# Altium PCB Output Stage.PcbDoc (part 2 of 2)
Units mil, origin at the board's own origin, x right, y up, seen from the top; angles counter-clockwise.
Board outline 5000 x 8750 mil, 6 copper layers (Top Layer, Layer 1, Layer 2, Layer 3, Layer 4, Bottom Layer), stack 91 mil thick; 55 components, 34 nets, 272 pads, 65 vias.
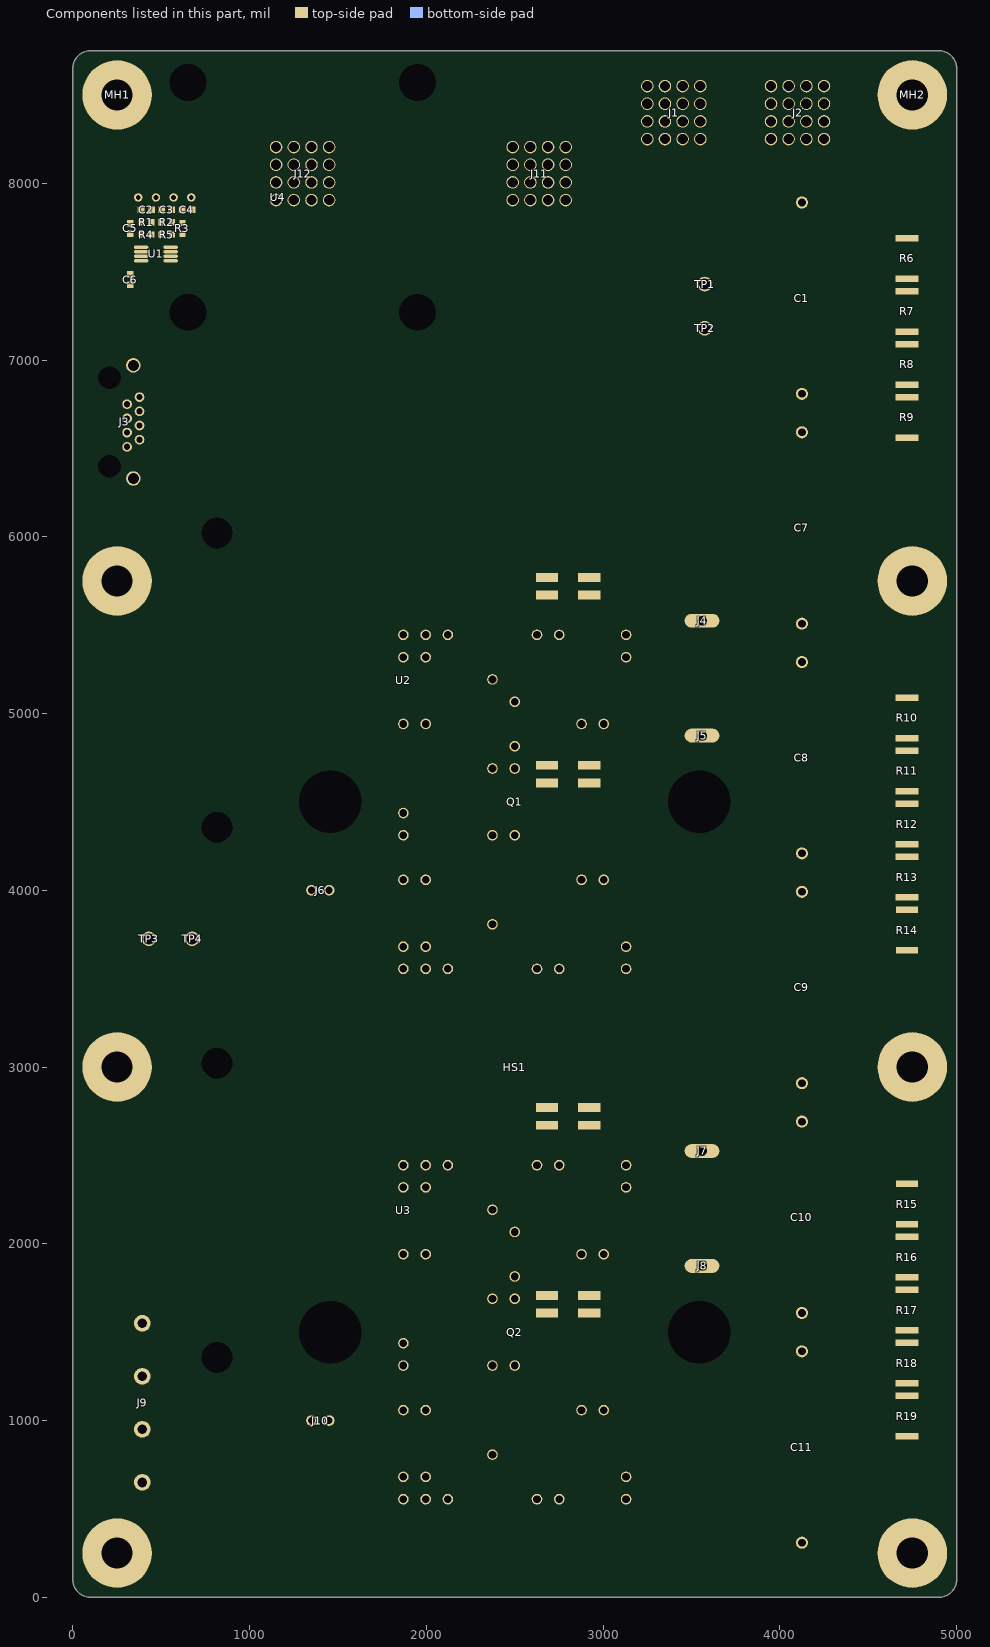
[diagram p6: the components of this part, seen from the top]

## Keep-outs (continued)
Layer 3:
  circle w15: c3501,5525 r47.17
  circle w15: c3619,5525 r47.17
  circle w15: c3501,2525 r47.17
  circle w15: c3619,2525 r47.17
  region: 2146.02,7015 2146.02,7525 2060,7525 2060,7015
  region: 2148.23,6965 2148.23,7578.68 2117.62,7578.68 2117.62,6965
  rectangle: 3965,2695 4285,2910
  rectangle: 3965,5295 4285,5510
  region: 2530.34,3795.34 2530.34,4045.34 2355,4045.34 2355,3795.34
  region: 2530.34,795.34 2530.34,1045.34 2355,1045.34 2355,795.34
  rectangle: 3035.75,1265.75 3400,1505
  rectangle: 3035.75,4265.75 3400,4505
  rectangle: 2935.34,1649.66 3185.34,1709.66
  rectangle: 2935,4650 3185,4710
  rectangle: 3500,5470 3620,5580
  rectangle: 3500,2470 3620,2580
  region: 3335.22,1875 3784.78,1875 3816.99,1546.5 3269.63,1546.5
  region: 3335.22,4875 3784.78,4875 3816.99,4546.5 3269.63,4546.5
  lines w10: 195,2585 cw(c295,2585) 295,2685 ; 195,3415 ccw(c295,3415) 295,3315 ; 625,7045.79 cw(c625,6945.79) 725,6945.79 ; 625,7495 ccw(c625,7595) 725,7595 ; 1955,7045.79 cw(c1955,6845.79) 2155,6845.79 ; 1955,7495 ccw(c1955,7695) 2155,7695 ; 1990,815 cw(c1990,765) 2040,765 ; 2072.64,756.36 cw(c2108,721) 2143.36,756.36 ; 2315,562 cw(c2415,562) 2415,662 ; 2315,3562 cw(c2415,3562) 2415,3662 ; 2525,965 cw(c2575,965) 2575,1015 ; 2525,3965 cw(c2575,3965) 2575,4015 ; 2790,1225 cw(c2840,1225) 2840,1275 ; 2790,4225 cw(c2840,4225) 2840,4275 ; 3870,195 ccw(c3870,295) 3970,295 ; 4275,275 ccw(c4355,275) 4355,195 ccw(c4355,275) 4435,275 ; 4705,565 ccw(c4705,665) 4805,665 ; 4705,2685 cw(c4705,2585) 4805,2585 ; 4705,3315 ccw(c4705,3415) 4805,3415 ; 4705,5435 cw(c4705,5335) 4805,5335 ; 4705,6065 ccw(c4705,6165) 4805,6165
Bottom Layer:
  circle w15: c3501,5525 r47.17
  circle w15: c3619,5525 r47.17
  circle w15: c3501,2525 r47.17
  circle w15: c3619,2525 r47.17
  rectangle: 3500,5470 3620,5580
  rectangle: 3500,2470 3620,2580
  region: 3301.15,4875 3816.99,4875 3816.99,4546.5 3269.63,4546.5
  region: 3301.15,1875 3816.99,1875 3816.99,1546.5 3269.63,1546.5
  lines w10: 195,2550 cw(c295,2550) 295,2650 ; 2315,572.17 cw(c2365,572.17) 2365,622.17 ; 2315,1042 ccw(c2365,1042) 2365,992 ; 2315,3572.17 cw(c2365,3572.17) 2365,3622.17 ; 2315,4042 ccw(c2365,4042) 2365,3992 ; 3835,195 ccw(c3835,295) 3935,295 ; 4305,245 ccw(c4355,245) 4355,195 ; 4348,195 ccw(c4348,245) 4398,245 ; 4705,600 ccw(c4705,700) 4805,700 ; 4705,2650 cw(c4705,2550) 4805,2550 ; 4705,3350 ccw(c4705,3450) 4805,3450 ; 4705,5400 cw(c4705,5300) 4805,5300 ; 4705,6100 ccw(c4705,6200) 4805,6200

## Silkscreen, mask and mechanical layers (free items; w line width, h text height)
Top Overlay:
  drawing of 107 lines, arcs and shapes, not listed
  text "-" at 4051.54,8013.08 h400
  text "+" at 3315.44,7978.62 h400
  text "A" at 1180.17,7550 h400
  text "B" at 2541.8,7550 h400
  text "+" at 3346.52,7329.71 h180
  text "-" at 3346.52,7064.71 h180
  text "A" at 336.52,3494.71 h180
  text "B" at 581.52,3494.71 h180
  text "WOLFPACK 60KW DAB (OUTPUT STAGE) / PN CRD60DD12N-GMA, V1 10/2023" at 363.05,55 h180
Mechanical 1:
  rectangle: 0,3500 5000,8500
Board Outline:
  the board outline again, w1
Drill Drawing:
  drawing of 171 lines, arcs and shapes, not listed
  text "*" at 150,11885 h60
  text "THESE HOLES (1.10MM +/- 0.05MM) ARE FOR PRESS-FIT PART. USE 47.2MIL +/- 1MIL DRILLED HOLES. COPPER THICKNESS IN HOLE 25-50UM." at 242.5,11827.5 h100
  text "w" at 16.81,11802.22 h200
  text "^" at 155,11700.01 h60
  text "THESE HOLES (1.48MM +/- 0.05MM) ARE FOR PRESS-FIT PART. USE 63.0MIL +/- 1MIL DRILLED HOLES. COPPER THICKNESS IN HOLE 25-60UM." at 247.5,11632.5 h100
  text "w" at 23.35,11614.16 h200
  text "Symbol" at 97.5,11452.5 h72
  text "Count" at 603.38,11452.5 h72
  text "Hole Size" at 1203.22,11452.5 h72
  text "Plated" at 2302.9,11452.5 h72
  text "Hole Type" at 2808.77,11452.5 h72
  text "Drill Layer Pair" at 3542.57,11452.5 h72
  text "Via/Pad" at 5042.13,11452.5 h72
  text "Pad Shape" at 5631.97,11452.5 h72
  text "Hole Tolerance (+)" at 6377.77,11452.5 h72
  text "Hole Tolerance (-)" at 7711.38,11452.5 h72
  text "65" at 603.38,11302.5 h60
  text "0.51mm (20.00mil)" at 1203.22,11302.5 h60
  text "PTH" at 2302.9,11302.5 h60
  text "Round" at 2808.77,11302.5 h60
  text "Top Layer - Bottom Layer" at 3542.57,11302.5 h60
  text "Via" at 5042.13,11302.5 h60
  text "Rounded" at 5631.97,11302.5 h60
  text "0.08mm (3.00mil)" at 6377.77,11302.5 h60
  text "0.08mm (3.00mil)" at 7711.38,11302.5 h60
  text "4" at 603.38,11152.5 h60
  text "0.70mm (27.56mil)" at 1203.22,11152.5 h60
  text "PTH" at 2302.9,11152.5 h60
  text "Round" at 2808.77,11152.5 h60
  text "Top Layer - Bottom Layer" at 3542.57,11152.5 h60
  text "Pad" at 5042.13,11152.5 h60
  text "Rounded" at 5631.97,11152.5 h60
  text "0.08mm (3.00mil)" at 6377.77,11152.5 h60
  text "0.08mm (3.00mil)" at 7711.38,11152.5 h60
  text "8" at 603.38,11002.5 h60
  text "0.89mm (35.04mil)" at 1203.22,11002.5 h60
  text "PTH" at 2302.9,11002.5 h60
  text "Round" at 2808.77,11002.5 h60
  text "Top Layer - Bottom Layer" at 3542.57,11002.5 h60
  text "Pad" at 5042.13,11002.5 h60
  text "Rounded" at 5631.97,11002.5 h60
  text "0.08mm (3.00mil)" at 6377.77,11002.5 h60
  text "0.08mm (3.00mil)" at 7711.38,11002.5 h60
  text "4" at 603.38,10852.5 h60
  text "1.02mm (40.16mil)" at 1203.22,10852.5 h60
  text "PTH" at 2302.9,10852.5 h60
  text "Round" at 2808.77,10852.5 h60
  text "Top Layer - Bottom Layer" at 3542.57,10852.5 h60
  text "Pad" at 5042.13,10852.5 h60
  text "Rounded" at 5631.97,10852.5 h60
  text "0.08mm (3.00mil)" at 6377.77,10852.5 h60
  text "0.08mm (3.00mil)" at 7711.38,10852.5 h60
  text "*" at -75,10755 h60
  text "72" at 603.38,10702.5 h60
  text "1.10mm (43.31mil)" at 1203.22,10702.5 h60
  text "PTH" at 2302.9,10702.5 h60
  text "Round" at 2808.77,10702.5 h60
  text "Top Layer - Bottom Layer" at 3542.57,10702.5 h60
  text "Pad" at 5042.13,10702.5 h60
  text "Rounded" at 5631.97,10702.5 h60
  text "0.05mm (1.97mil)" at 6377.77,10702.5 h60
  text "0.05mm (1.97mil)" at 7711.38,10702.5 h60
  text "A" at 68.41,10692.51 h66.67
  text "w" at -205.69,10674.72 h200
  text "12" at 603.38,10552.5 h60
  text "1.10mm (43.31mil)" at 1203.22,10552.5 h60
  text "PTH" at 2302.9,10552.5 h60
  text "Round" at 2808.77,10552.5 h60
  text "Top Layer - Bottom Layer" at 3542.57,10552.5 h60
  text "Pad" at 5042.13,10552.5 h60
  text "Rounded" at 5631.97,10552.5 h60
  text "0.08mm (3.00mil)" at 6377.77,10552.5 h60
  text "0.08mm (3.00mil)" at 7711.38,10552.5 h60
  text "8" at 603.38,10402.5 h60
  text "1.40mm (55.12mil)" at 1203.22,10402.5 h60
  text "PTH" at 2302.9,10402.5 h60
  text "Round" at 2808.77,10402.5 h60
  text "Top Layer - Bottom Layer" at 3542.57,10402.5 h60
  text "Pad" at 5042.13,10402.5 h60
  text "Rounded" at 5631.97,10402.5 h60
  text "0.08mm (3.00mil)" at 6377.77,10402.5 h60
  text "0.08mm (3.00mil)" at 7711.38,10402.5 h60
  text "^" at -84.38,10320.84 h60
  text "64" at 603.38,10252.5 h60
  text "1.48mm (58.07mil)" at 1203.22,10252.5 h60
  text "PTH" at 2302.9,10252.5 h60
  text "Round" at 2808.77,10252.5 h60
  text "Top Layer - Bottom Layer" at 3542.57,10252.5 h60
  text "Pad" at 5042.13,10252.5 h60
  text "Rounded" at 5631.97,10252.5 h60
  text "0.05mm (1.97mil)" at 6377.77,10252.5 h60
  text "0.05mm (1.97mil)" at 7711.38,10252.5 h60
  text "w" at -213.52,10237.49 h200
  text "2" at 603.38,10102.5 h60
  text "1.57mm (61.81mil)" at 1203.22,10102.5 h60
  text "PTH" at 2302.9,10102.5 h60
  text "Round" at 2808.77,10102.5 h60
  text "Top Layer - Bottom Layer" at 3542.57,10102.5 h60
  text "Pad" at 5042.13,10102.5 h60
  text "Rounded" at 5631.97,10102.5 h60
  text "0.08mm (3.00mil)" at 6377.77,10102.5 h60
  text "0.08mm (3.00mil)" at 7711.38,10102.5 h60
  text "4" at 603.38,9952.5 h60
  text "1.60mm (62.99mil)" at 1203.22,9952.5 h60
  text "PTH" at 2302.9,9952.5 h60
  text "Round" at 2808.77,9952.5 h60
  text "Top Layer - Bottom Layer" at 3542.57,9952.5 h60
  text "Pad" at 5042.13,9952.5 h60
  text "Rounded" at 5631.97,9952.5 h60
  text "0.08mm (3.00mil)" at 6377.77,9952.5 h60
  text "0.08mm (3.00mil)" at 7711.38,9952.5 h60
  text "2" at 603.38,9802.5 h60
  text "3.25mm (127.95mil)" at 1203.22,9802.5 h60
  text "NPTH" at 2302.9,9802.5 h60
  text "Round" at 2808.77,9802.5 h60
  text "Top Layer - Bottom Layer" at 3542.57,9802.5 h60
  text "Pad" at 5042.13,9802.5 h60
  text "Rounded" at 5631.97,9802.5 h60
  text "0.13mm (5.00mil)" at 6377.77,9802.5 h60
  text "0.13mm (5.00mil)" at 7711.38,9802.5 h60
  text "4" at 603.38,9652.5 h60
  text "4.45mm (175.00mil)" at 1203.22,9652.5 h60
  text "NPTH" at 2302.9,9652.5 h60
  text "Round" at 2808.77,9652.5 h60
  text "Top Layer - Bottom Layer" at 3542.57,9652.5 h60
  text "Pad" at 5042.13,9652.5 h60
  text "Rounded" at 5631.97,9652.5 h60
  text "0.13mm (5.00mil)" at 6377.77,9652.5 h60
  text "0.13mm (5.00mil)" at 7711.38,9652.5 h60
  text "8" at 603.38,9502.5 h60
  text "4.50mm (177.17mil)" at 1203.22,9502.5 h60
  text "PTH" at 2302.9,9502.5 h60
  text "Round" at 2808.77,9502.5 h60
  text "Top Layer - Bottom Layer" at 3542.57,9502.5 h60
  text "Pad" at 5042.13,9502.5 h60
  text "Rounded" at 5631.97,9502.5 h60
  text "0.13mm (5.00mil)" at 6377.77,9502.5 h60
  text "0.13mm (5.00mil)" at 7711.38,9502.5 h60
  text "4" at 603.38,9352.5 h60
  text "5.30mm (208.66mil)" at 1203.22,9352.5 h60
  text "NPTH" at 2302.9,9352.5 h60
  text "Round" at 2808.77,9352.5 h60
  text "Top Layer - Bottom Layer" at 3542.57,9352.5 h60
  text "Pad" at 5042.13,9352.5 h60
  text "Rounded" at 5631.97,9352.5 h60
  text "0.13mm (5.00mil)" at 6377.77,9352.5 h60
  text "0.13mm (5.00mil)" at 7711.38,9352.5 h60
  text "4" at 603.38,9202.5 h60
  text "9.00mm (354.33mil)" at 1203.22,9202.5 h60
  text "NPTH" at 2302.9,9202.5 h60
  text "Round" at 2808.77,9202.5 h60
  text "Top Layer - Bottom Layer" at 3542.57,9202.5 h60
  text "Pad" at 5042.13,9202.5 h60
  text "Rounded" at 5631.97,9202.5 h60
  text "0.13mm (5.00mil)" at 6377.77,9202.5 h60
  text "0.13mm (5.00mil)" at 7711.38,9202.5 h60
  text "265 Total" at 603.38,9052.5 h60

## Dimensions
100,0 to 100,8750 on Drill Drawing
0,100 to 5000,100 on Drill Drawing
